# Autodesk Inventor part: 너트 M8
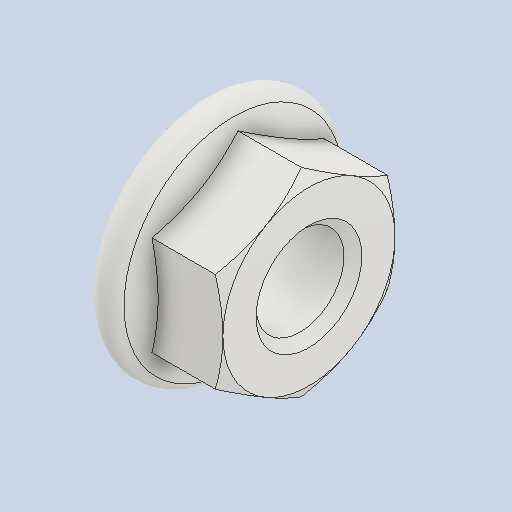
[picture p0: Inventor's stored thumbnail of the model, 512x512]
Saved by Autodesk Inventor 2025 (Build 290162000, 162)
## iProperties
Created: 2024-07
Part Number: 너트 M8
Material: 스테인리스강
Description: 플랜지붙이 6각 너트 - 일반 스레드
Document SubType Name: Modeling
Designer: myung
Density: 8 g/cm^3
Appearance: 기본값
Author: jhkim
Sending System: Autodesk Inventor 2025
Preprocessor: ST-DEVELOPER v20
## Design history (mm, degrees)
feature "Solid1"
node "솔리드1"
